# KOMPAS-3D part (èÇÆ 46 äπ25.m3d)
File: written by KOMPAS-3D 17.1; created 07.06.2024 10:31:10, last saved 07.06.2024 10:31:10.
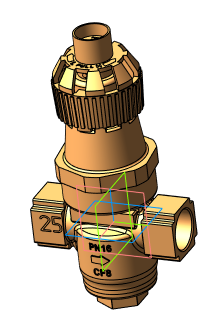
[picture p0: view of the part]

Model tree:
1. Операция без истории:1  (labels: Сталь 20  ГОСТ 1050-2013)

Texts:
  ООО АДЛ Групп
